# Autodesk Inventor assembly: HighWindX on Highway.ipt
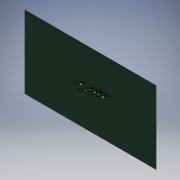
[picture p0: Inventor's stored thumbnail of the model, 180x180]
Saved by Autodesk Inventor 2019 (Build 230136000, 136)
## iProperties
Created: 2018-12
Part Number: HighWindX on Highway.ipt
Document SubType Name: Assembly
Designer: Patel Family
Author: Patel Family
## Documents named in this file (4)
- A:\Documents\Inventor Files\HighWindX on Highway.ipt.iam
- A:\Documents\Inventor Files\Highway.ipt
- A:\Documents\Inventor Files\HighWindX.ipt.iam
- HighWindX.ipt
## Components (7 placed, 2 different names)
1. Highway:1 — Mate:1, Mate:2, Mate:3, Mate:4, Mate:5
2. HighWindX.ipt:1 [sub-assembly] — Mate:1
3. HighWindX.ipt:2 [sub-assembly]
4. HighWindX.ipt:3 [sub-assembly] — Mate:5
5. HighWindX.ipt:4 [sub-assembly] — Mate:4
6. HighWindX.ipt:5 [sub-assembly] — Mate:3
7. HighWindX.ipt:6 [sub-assembly] — Mate:2
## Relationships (5: Mate 5)
- Mate:1: Highway:1 ↔ HighWindX.ipt:1
- Mate:2: Highway:1 ↔ HighWindX.ipt:6
- Mate:3: Highway:1 ↔ HighWindX.ipt:5
- Mate:4: Highway:1 ↔ HighWindX.ipt:4
- Mate:5: Highway:1 ↔ HighWindX.ipt:3
